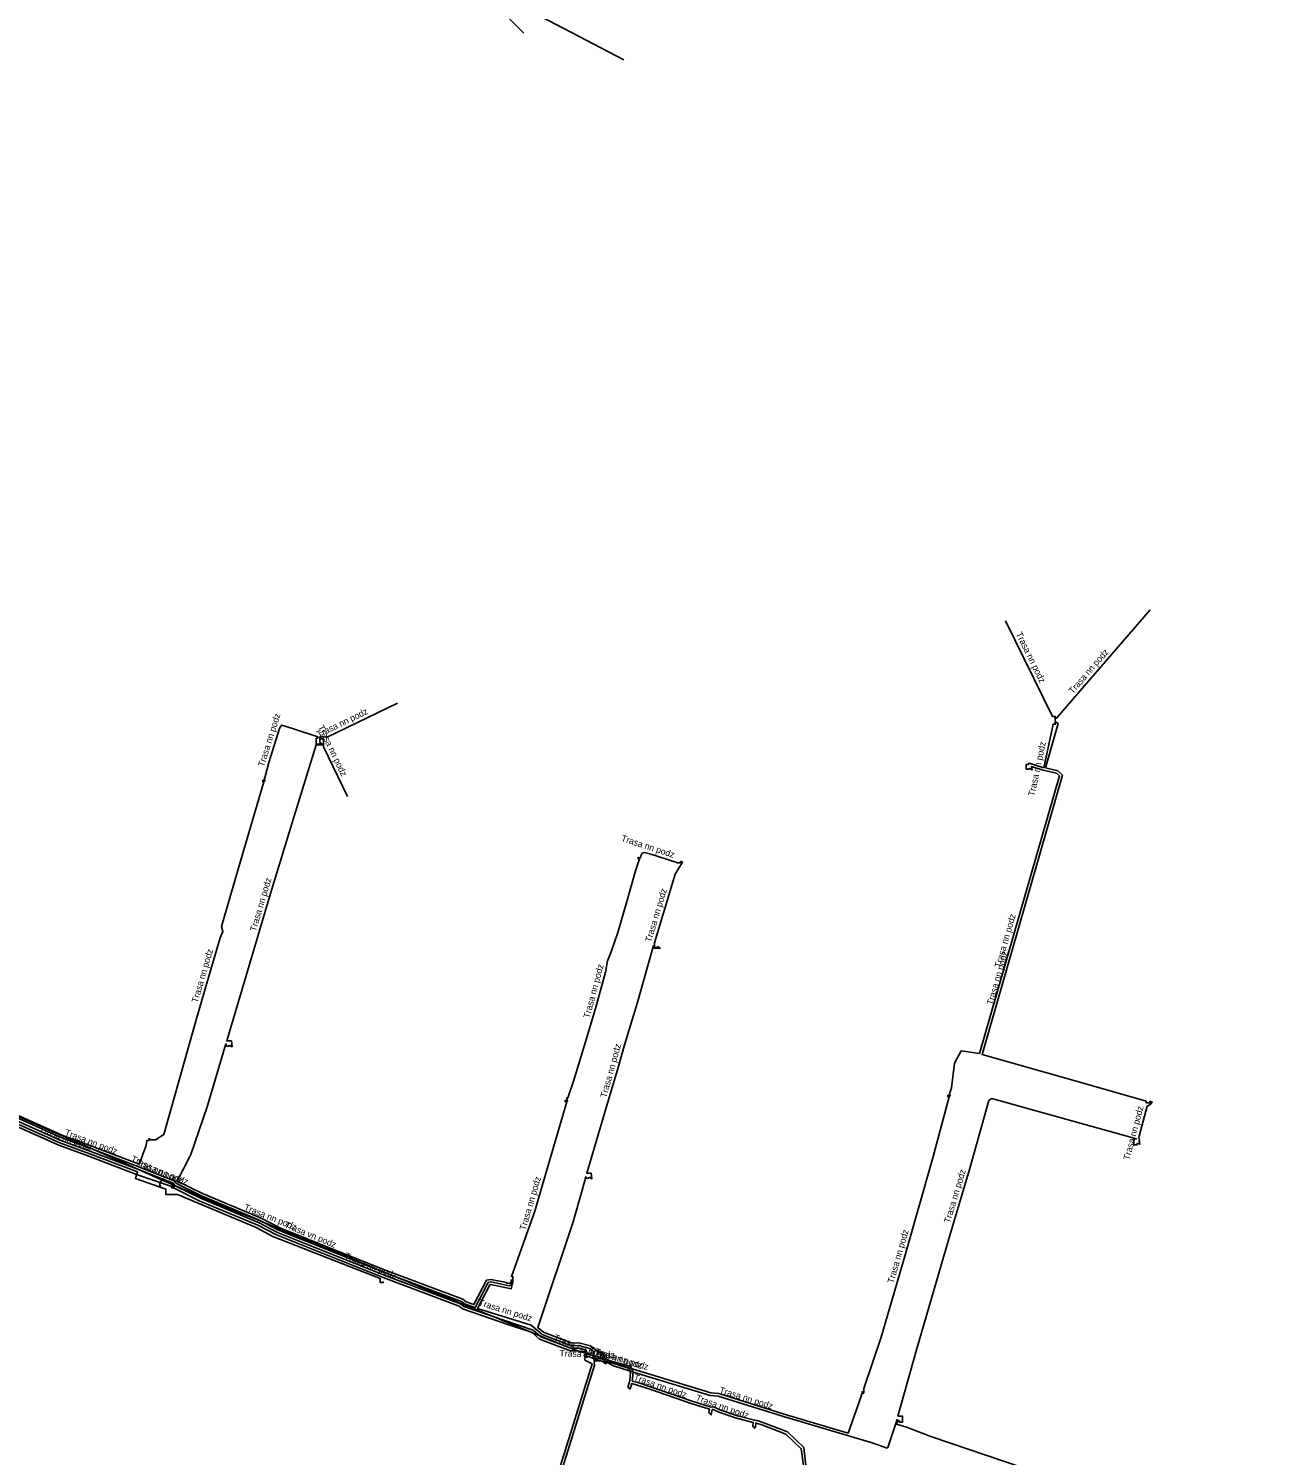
# Model space of a CAD drawing. Extents: x -742082 to -717476, y -1040737 to -1024597.
# Drawn here: x -735689.8 to -735497.8, y -1032337.1 to -1032117.1 of the extents above; entities that cross this region are included whole.
import ezdxf

# ---------------------------------------------------------------- set-up
doc = ezdxf.new("R2010")
doc.units = 0
for name, color, linetype in [('Level 15', 7, 'Continuous'), ('Level 20', 7, 'Continuous'), ('Level 25', 7, 'Continuous')]:
    doc.layers.add(name, color=color, linetype=linetype)

msp = doc.modelspace()

# ---------------------------------------------------------------- linework, layer by layer
at = {"layer": 'Level 15'}
for points in [[(-735621.57, -1032109.49), (-735621.21, -1032109.76), (-735598, -1032121.9)], [(-735621.57, -1032109.49), (-735621.33, -1032109.86), (-735613.4, -1032117.8)], [(-735531.46, -1032223.89), (-735531.46, -1032223.15), (-735531.87, -1032223.15), (-735539.1, -1032208.4)], [(-735531.44, -1032223.89), (-735531.44, -1032223.45), (-735531.25, -1032223.45), (-735516.8, -1032206.7)], [(-735644.86, -1032227.06), (-735644.86, -1032226.32), (-735644.29, -1032226.32), (-735643.73, -1032226.38), (-735632.9, -1032221.1)], [(-735653.67, -1032232.96), (-735653.32, -1032233.12), (-735653.41, -1032232.62), (-735653.34, -1032232.63), (-735652.7, -1032230.25), (-735651.07, -1032225.02), (-735650.75, -1032224.48), (-735649.07, -1032225.02), (-735645.16, -1032226.33), (-735645.19, -1032226.52), (-735645.4, -1032226.52), (-735645.4, -1032227.43), (-735644.85, -1032227.43), (-735644.85, -1032227.17)], [(-735531.45, -1032224), (-735531, -1032224.26), (-735532.95, -1032231.09), (-735531.06, -1032231.55), (-735530.35, -1032232.2), (-735542.73, -1032275.31), (-735540.55, -1032275.89), (-735528.04, -1032279.47), (-735517.41, -1032282.48), (-735517.41, -1032282.73), (-735516.86, -1032282.73), (-735516.86, -1032282.47)], [(-735535.47, -1032231.14), (-735535.47, -1032231.3), (-735535.92, -1032231.3), (-735535.92, -1032230.59), (-735535.61, -1032230.59), (-735535.47, -1032230.34), (-735533.21, -1032231.07), (-735531.79, -1032224.36), (-735531.45, -1032224.36), (-735531.45, -1032224)], [(-735644.85, -1032227.17), (-735644.3, -1032227.53), (-735645.44, -1032227.53), (-735648.59, -1032237.86), (-735652.45, -1032250.46), (-735656.41, -1032263.84), (-735659.21, -1032273.19), (-735658.49, -1032273.19), (-735658.4, -1032274.1), (-735658.85, -1032273.84)], [(-735644.84, -1032227.06), (-735644.84, -1032226.62), (-735644.29, -1032226.62), (-735644.29, -1032227.83), (-735640.6, -1032235.5)], [(-735548.01, -1032281.57), (-735547.66, -1032281.73), (-735547.76, -1032281.34), (-735547.43, -1032280.41), (-735546.96, -1032276.6), (-735545.95, -1032274.72), (-735543.15, -1032275.12), (-735530.8, -1032232.33), (-735531.26, -1032231.91), (-735531.26, -1032231.91), (-735533.54, -1032231.38), (-735535.12, -1032230.88), (-735535.02, -1032231.4), (-735535.47, -1032231.14)], [(-735671.14, -1032288.17), (-735671.14, -1032288.44), (-735670.2, -1032288.45), (-735668.91, -1032287.63), (-735666.17, -1032277.97), (-735663.75, -1032269.23), (-735662.01, -1032263.4), (-735660.23, -1032257.3), (-735659.8, -1032256.3), (-735660.02, -1032255.55), (-735657.09, -1032245.5), (-735653.51, -1032233.22), (-735653.67, -1032233.22), (-735653.67, -1032232.96)], [(-735607.04, -1032282.32), (-735606.68, -1032282.48), (-735606.78, -1032281.95), (-735606.6, -1032281.96), (-735605.67, -1032279.23), (-735604.24, -1032274.53), (-735602.33, -1032268.18), (-735600.83, -1032262.57), (-735600.52, -1032260.82), (-735599.86, -1032259.32), (-735598.91, -1032256.46), (-735597.53, -1032251.7), (-735596.17, -1032246.95), (-735595.56, -1032245.1), (-735595.77, -1032245.1), (-735595.77, -1032244.84)], [(-735595.77, -1032244.84), (-735595.42, -1032245), (-735595.36, -1032244.63), (-735595.15, -1032244.24), (-735594.81, -1032244.12), (-735593.98, -1032244.33), (-735589.81, -1032245.69), (-735589.81, -1032245.72), (-735589.26, -1032245.72), (-735589.26, -1032245.46)], [(-735589.26, -1032245.46), (-735588.91, -1032245.62), (-735590.07, -1032247.46), (-735593.26, -1032258.09), (-735593.25, -1032258.1), (-735593.25, -1032258.78), (-735592.8, -1032258.78), (-735592.8, -1032258.62)], [(-735730.92, -1032256.41), (-735730.57, -1032256.57), (-735730.66, -1032256.42), (-735729.08, -1032257.32), (-735724.8, -1032259.88), (-735724.34, -1032260.46), (-735725.53, -1032263.71), (-735727.82, -1032267.87), (-735712.19, -1032274.84), (-735710.38, -1032275.41), (-735707.73, -1032276.57), (-735703.38, -1032278.99), (-735693.42, -1032283.78), (-735684.51, -1032287.78), (-735679.9, -1032289.47), (-735672.72, -1032292.2), (-735671.65, -1032289.29), (-735671.56, -1032288.54), (-735671.19, -1032288.54), (-735671.19, -1032288.17)], [(-735592.8, -1032258.62), (-735592.35, -1032258.88), (-735593.35, -1032258.88), (-735593.35, -1032258.48), (-735593.38, -1032258.48), (-735595.94, -1032267.43), (-735597.82, -1032273.62), (-735598.84, -1032277.31), (-735600.35, -1032282.28), (-735603.7, -1032293.56), (-735603.03, -1032293.56), (-735602.93, -1032294.46), (-735603.38, -1032294.2)], [(-735729.51, -1032270.59), (-735729.51, -1032271.26), (-735728.84, -1032271.26), (-735728.84, -1032269.91), (-735728.12, -1032269.05), (-735712.61, -1032275.96), (-735710.81, -1032276.54), (-735708.26, -1032277.65), (-735703.94, -1032280.05), (-735693.93, -1032284.87), (-735684.96, -1032288.89), (-735680.32, -1032290.6), (-735672.96, -1032293.39), (-735673.31, -1032294.41), (-735668.59, -1032296.03), (-735668.6, -1032296.88), (-735666.8, -1032296.88), (-735654.68, -1032301.96), (-735652.11, -1032303.35), (-735635.55, -1032309.82), (-735635.55, -1032310.46), (-735635.1, -1032310.46), (-735635.1, -1032310.3)], [(-735729.45, -1032270.59), (-735729.45, -1032271.06), (-735729.04, -1032271.06), (-735729.04, -1032270.77), (-735728.01, -1032269.54), (-735712.76, -1032276.33), (-735710.95, -1032276.91), (-735708.44, -1032278.01), (-735704.12, -1032280.41), (-735694.1, -1032285.23), (-735685.11, -1032289.26), (-735680.46, -1032290.97), (-735673.11, -1032293.77), (-735667.69, -1032295.64), (-735667.69, -1032295.83), (-735667.36, -1032295.83), (-735667.35, -1032295.56)], [(-735658.85, -1032273.84), (-735658.85, -1032274), (-735659.3, -1032274), (-735659.3, -1032273.68), (-735659.35, -1032273.66), (-735662.25, -1032283.33), (-735664.75, -1032290.68), (-735664.84, -1032290.92), (-735666.86, -1032294.81), (-735662.95, -1032296.73), (-735653.9, -1032300.54), (-735651.04, -1032302), (-735642.34, -1032305.49), (-735634.64, -1032308.57), (-735622.8, -1032313.02), (-735622.27, -1032313.43), (-735621.1, -1032313.83), (-735619.15, -1032310.06), (-735618.45, -1032309.96), (-735616.09, -1032310.43), (-735616.09, -1032310.54), (-735615.34, -1032310.54), (-735615.34, -1032309.97)], [(-735615.27, -1032309.97), (-735615.27, -1032310.24), (-735615.08, -1032310.24), (-735615.08, -1032309.53), (-735615.32, -1032309.53), (-735611.76, -1032299.59), (-735608.82, -1032289.56), (-735606.79, -1032282.58), (-735607.04, -1032282.58), (-735607.04, -1032282.32)], [(-735561.18, -1032327.21), (-735561.18, -1032327.48), (-735560.98, -1032327.48), (-735560.98, -1032326.77), (-735558.31, -1032318.86), (-735554.65, -1032306.4), (-735550.32, -1032291.22), (-735547.8, -1032281.83), (-735548.01, -1032281.83), (-735548.01, -1032281.57)], [(-735518.77, -1032288.96), (-735518.86, -1032289.22), (-735519.32, -1032289.22), (-735519.32, -1032288.31), (-735518.92, -1032288.31), (-735529.79, -1032285.25), (-735541.23, -1032282.08), (-735541.69, -1032282.39), (-735544.66, -1032293.04), (-735547.87, -1032303.7), (-735552.83, -1032320.82), (-735555.7, -1032331.06), (-735554.99, -1032331.06), (-735554.99, -1032331.97), (-735555.49, -1032331.97), (-735555.49, -1032331.77)], [(-735516.86, -1032282.47), (-735516.51, -1032282.63), (-735516.85, -1032283.02), (-735517.26, -1032283.23), (-735518.49, -1032287.89), (-735518.56, -1032288.09), (-735518.48, -1032288.48), (-735518.51, -1032288.53), (-735518.42, -1032289.12), (-735518.77, -1032288.96)], [(-735693.76, -1032284.51), (-735684.81, -1032288.52), (-735680.18, -1032290.22), (-735672.82, -1032293.02), (-735667.47, -1032295.14), (-735667.23, -1032295.46), (-735666.97, -1032295.65), (-735663.28, -1032297.46), (-735654.24, -1032301.26), (-735651.38, -1032302.73), (-735634.93, -1032309.31), (-735623.19, -1032313.72), (-735622.66, -1032314.14), (-735611.95, -1032317.81), (-735610.78, -1032318.81), (-735606.14, -1032320.58), (-735604.99, -1032320.56), (-735603.9, -1032320.84), (-735603.81, -1032320.83), (-735603.81, -1032321.46), (-735604.12, -1032321.66), (-735603.98, -1032321.9), (-735603.87, -1032321.8)], [(-735693.59, -1032284.14), (-735684.66, -1032288.15), (-735680.04, -1032289.85), (-735672.68, -1032292.65), (-735667.32, -1032294.77), (-735667.03, -1032295.11), (-735666.76, -1032295.3), (-735663.12, -1032297.1), (-735654.07, -1032300.9), (-735651.21, -1032302.37), (-735642.49, -1032305.86), (-735634.79, -1032308.94), (-735623, -1032313.37), (-735622.47, -1032313.79), (-735620.9, -1032314.31), (-735618.89, -1032310.43), (-735618.46, -1032310.36), (-735615.66, -1032310.93), (-735615.32, -1032310.8), (-735615.32, -1032309.97)], [(-735603.38, -1032294.2), (-735603.38, -1032294.36), (-735603.83, -1032294.36), (-735603.83, -1032294.14), (-735603.86, -1032294.14), (-735604.29, -1032295.86), (-735605.78, -1032301.09), (-735611.22, -1032317.38), (-735610.36, -1032318.11), (-735605.99, -1032319.78), (-735604.9, -1032319.76), (-735603.11, -1032320.21), (-735602.88, -1032320.5), (-735602.81, -1032320.53), (-735601.33, -1032321.4), (-735601.12, -1032321.86), (-735600.87, -1032322.13), (-735599.4, -1032322.94), (-735596.86, -1032323.72), (-735584.57, -1032327.45), (-735583.33, -1032327.55), (-735573.23, -1032330.72), (-735563.38, -1032333.65), (-735561.53, -1032328.43), (-735561.25, -1032327.58), (-735561.2, -1032327.58), (-735561.2, -1032327.21)], [(-735667.33, -1032295.56), (-735667.33, -1032295.71), (-735667.58, -1032295.71), (-735667.58, -1032295.42), (-735667.53, -1032295.42), (-735667.52, -1032295.27), (-735669.1, -1032294.55), (-735669.24, -1032294.59), (-735669.51, -1032295.18), (-735669.56, -1032295.18), (-735669.56, -1032295.53), (-735669.42, -1032295.53), (-735669.42, -1032295.41)], [(-735603.85, -1032321.8), (-735603.85, -1032321.89), (-735603.78, -1032321.89), (-735603.71, -1032321.36), (-735603.71, -1032321.08), (-735604.62, -1032321.08), (-735605.04, -1032320.96), (-735606.21, -1032320.98), (-735610.98, -1032319.16), (-735612.14, -1032318.17), (-735615.86, -1032316.9), (-735622.85, -1032314.5), (-735623.39, -1032314.08), (-735635.08, -1032309.69), (-735642.79, -1032306.6), (-735651.54, -1032303.1), (-735654.41, -1032301.62), (-735663.45, -1032297.83), (-735667.24, -1032295.96), (-735667.43, -1032295.88), (-735667.43, -1032295.56)], [(-735615.3, -1032309.97), (-735615.3, -1032310.34), (-735615.12, -1032310.34), (-735615.34, -1032311.4), (-735618.47, -1032310.77), (-735618.63, -1032310.79), (-735620.53, -1032314.45), (-735612.28, -1032317), (-735610.57, -1032318.46), (-735606.06, -1032320.18), (-735604.95, -1032320.16), (-735603.21, -1032320.6), (-735603.03, -1032320.87), (-735602.6, -1032321.02), (-735602.6, -1032322.12), (-735602.28, -1032322.12), (-735602.3, -1032322.46), (-735602.47, -1032322.45), (-735602.47, -1032322.25)], [(-735602.42, -1032322.25), (-735602.56, -1032322.76), (-735602.51, -1032323.16), (-735636.87, -1032433.66), (-735640.16, -1032432.53), (-735640.5, -1032432.2), (-735640.94, -1032432.05), (-735640.94, -1032432.36), (-735641.26, -1032432.36), (-735641.33, -1032431.81)], [(-735641.31, -1032431.81), (-735641.23, -1032432.26), (-735641.04, -1032432.26), (-735641.04, -1032431.6), (-735640.37, -1032431.82), (-735640.07, -1032432.14), (-735637.13, -1032433.14), (-735602.88, -1032323), (-735604, -1032322.4), (-735603.92, -1032321.8)], [(-735603.9, -1032321.8), (-735603.9, -1032321.93), (-735603.71, -1032321.93), (-735603.49, -1032321.85), (-735602.65, -1032322.16), (-735602.5, -1032322.39), (-735602.5, -1032322.25)], [(-735600.73, -1032322.84), (-735600.73, -1032322.97), (-735601.12, -1032322.7), (-735601.54, -1032322.53), (-735602.55, -1032322.5), (-735602.55, -1032322.35), (-735602.55, -1032322.25)], [(-735602.52, -1032322.25), (-735602.52, -1032322.42), (-735601.95, -1032322.22), (-735601.39, -1032322.22), (-735601.12, -1032322.44), (-735599.56, -1032323.31), (-735596.98, -1032324.1), (-735584.64, -1032327.84), (-735583.41, -1032327.94), (-735573.35, -1032331.11), (-735559.7, -1032335.16), (-735557.39, -1032335.98), (-735557.24, -1032335.9), (-735555.86, -1032331.74), (-735555.83, -1032331.58), (-735555.8, -1032331.59), (-735555.8, -1032331.87), (-735555.46, -1032331.87), (-735555.46, -1032331.77)], [(-735600.83, -1032322.84), (-735600.89, -1032322.92), (-735600.89, -1032322.74), (-735600.7, -1032322.7), (-735600.67, -1032322.57), (-735597.18, -1032323.71), (-735596.96, -1032324.31), (-735597.05, -1032325.56), (-735597.09, -1032325.73), (-735597.35, -1032326.57), (-735597.06, -1032326.83)], [(-735584.55, -1032330.75), (-735584.85, -1032330.51), (-735584.75, -1032329.98), (-735587.58, -1032329.1), (-735593.81, -1032326.94), (-735596.08, -1032326.21), (-735596.77, -1032326.02), (-735596.97, -1032326.69), (-735597.05, -1032326.89), (-735597.06, -1032326.83)], [(-735584.55, -1032330.75), (-735584.57, -1032330.82), (-735584.49, -1032330.82), (-735584.35, -1032330.04), (-735584.18, -1032330.03), (-735583.32, -1032330.43), (-735580.58, -1032331.38), (-735578.02, -1032332.03), (-735578.08, -1032332.65), (-735577.78, -1032332.87)], [(-735577.78, -1032332.87), (-735577.78, -1032332.91), (-735577.68, -1032332.69), (-735577.63, -1032332.11), (-735577.52, -1032332.13), (-735576.52, -1032332.44), (-735572.98, -1032333.83), (-735570.62, -1032336.06), (-735570.24, -1032339.03), (-735572.96, -1032346.92), (-735576.16, -1032355.55), (-735578.67, -1032362.3), (-735579.2, -1032363.46), (-735580.26, -1032366.52), (-735581.93, -1032371.15), (-735582.34, -1032371.01), (-735582.39, -1032371.24), (-735582.31, -1032371.4)], [(-735497.8, -1032351.29), (-735498.05, -1032351.08), (-735498.64, -1032351.82), (-735505.4, -1032349.31), (-735514.51, -1032346.22), (-735523.51, -1032343.43), (-735532.72, -1032340.36), (-735536.42, -1032339.02), (-735550.62, -1032334.2), (-735554.38, -1032332.77), (-735555.92, -1032332.26), (-735555.62, -1032331.68), (-735555.51, -1032331.86), (-735555.44, -1032331.77)]]:
    msp.add_lwpolyline(points, dxfattribs=at)
at = {"layer": 'Level 25'}
msp.add_lwpolyline([(-735569.84, -1032339.07), (-735570.24, -1032335.86), (-735572.76, -1032333.49), (-735576.38, -1032332.06), (-735577.42, -1032331.73), (-735577.77, -1032331.68), (-735580.46, -1032331), (-735583.17, -1032330.05), (-735584.1, -1032329.63), (-735584.49, -1032329.64), (-735587.46, -1032328.72), (-735593.69, -1032326.56), (-735595.96, -1032325.83), (-735596.69, -1032325.63), (-735596.56, -1032324.25), (-735596.88, -1032323.39), (-735600.8, -1032322.32), (-735605.67, -1032320.76), (-735611.31, -1032318.5), (-735618.41, -1032315.6), (-735626.46, -1032312.31), (-735635.82, -1032308.5), (-735642.16, -1032305.81), (-735643.5, -1032305.31), (-735644.09, -1032305.04), (-735655.33, -1032300.43), (-735657.4, -1032299.64), (-735663.11, -1032297.22), (-735663.53, -1032297.06), (-735669.3, -1032294.59), (-735677.78, -1032290.8), (-735688.44, -1032286.12), (-735702.59, -1032279.88)], dxfattribs=at)

# ---------------------------------------------------------------- texts
at = {"layer": 'Level 20'}
for s, rotation, p in [('Trasa nn podz', 296.1049, (-735537.55, -1032210.43)), ('Trasa nn podz', 49.2174, (-735528.72, -1032219.75)), ('Trasa nn podz', 72.6154, (-735653.47, -1032231.01)), ('Trasa nn podz', 25.9861, (-735645.03, -1032226.45)), ('Trasa nn podz', 295.7168, (-735645.2, -1032224.79)), ('Trasa nn podz', 78.0458, (-735534.66, -1032235.52)), ('Trasa nn podz', 341.8848, (-735598.47, -1032242.34)), ('Trasa nn podz', 73.4955, (-735654.72, -1032256.39)), ('Trasa nn podz', 73.2983, (-735593.77, -1032258.05)), ('Trasa nn podz', 73.9082, (-735539.88, -1032261.98)), ('Trasa nn podz', 73.671, (-735663.7, -1032267.39)), ('Trasa nn podz', 73.9772, (-735541.08, -1032267.75)), ('Trasa nn podz', 75.0838, (-735603.27, -1032269.77)), ('Trasa nn podz', 74.4591, (-735600.67, -1032282.03)), ('Trasa nn podz', 75.1772, (-735520, -1032291.65)), ('Trasa nn podz', 339.8218, (-735688.21, -1032287.16)), ('Trasa nn podz', 339.1761, (-735684.28, -1032287.7)), ('Trasa nn podz', 335.4551, (-735674.08, -1032291.73)), ('Trasa nn podz', 338.3947, (-735673.34, -1032292.28)), ('Trasa nn podz', 73.637, (-735613.13, -1032302.47)), ('Trasa nn podz', 73.2455, (-735547.69, -1032301.36)), ('Trasa nn podz', 338.1533, (-735656.63, -1032299.22)), ('Trasa vn podz', 337.6994, (-735650.41, -1032301.91)), ('Trasa nn podz', 74.0724, (-735556.38, -1032310.64)), ('Trasa nn podz', 338.2151, (-735641.15, -1032306.72)), ('Trasa nn podz', 342.837, (-735620.46, -1032313.95)), ('Trasa nn podz', 339.8009, (-735608.86, -1032319.34)), ('Trasa nn podz', 341.936, (-735603.44, -1032321.14)), ('Trasa nn podz', 343.1432, (-735602.52, -1032321.48)), ('Trasa nn podz', 358.191, (-735607.91, -1032321.83)), ('Trasa nn podz', 340.8809, (-735596.55, -1032325.46)), ('Trasa nn podz', 342.5289, (-735583.34, -1032327.44)), ('Trasa nn podz', 340.7463, (-735586.98, -1032328.62))]:
    msp.add_text(s, height=1, rotation=rotation, dxfattribs=at).set_placement(p)

doc.saveas('drawing.dxf')
